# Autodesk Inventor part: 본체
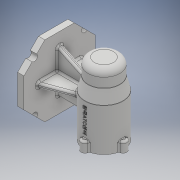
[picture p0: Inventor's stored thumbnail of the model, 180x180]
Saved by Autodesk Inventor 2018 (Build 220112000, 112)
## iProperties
Created: 2019-12
Part Number: 본체
Material: Generic
Document SubType Name: Modeling
Designer: Administrator
Density: 1 g/cm^3
Appearance: Default
Author: Administrator
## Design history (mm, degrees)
sketch "스케치1" dims "d0" = 112
  geometry: L1 (56, -23.196)-(23.196, -56); L2 (23.196, -56)-(-23.196, -56); L3 (-23.196, -56)-(-56, -23.196); L4 (-56, -23.196)-(-56, 23.196); L5 (-56, 23.196)-(-23.196, 56); L6 (-23.196, 56)-(23.196, 56); L7 (23.196, 56)-(56, 23.196); L8 (56, 23.196)-(56, -23.196); 5 further points
  constraints: 16 end point, 3 coincident, 1 horizontal alignment, 1 midpoint, 19 other
extrude "돌출1" new body sketch "스케치1" distance "d1" = 10; taper "d2" = 0 deg
sketch "스케치3"
  geometry: L1 (0, 0)-(-80, 0); L2 (-80, 0)-(-80, -56); L3 (-80, -56)-(-110, -56); L4 (-110, -56)-(-110, -40); L5 (-110, -40)-(-80, -40); L6 (-80, -40)-(-80, -56); L7 (-80, -40)-(-110, -40); L8 (-110, -40)-(-110, 11); L9 (-110, 11)-(-80, 11); L10 (-80, 11)-(-80, -40); L11 (-80, 0)-(-80, 56); L12 (-80, 56)-(-105, 56); L13 (-105, 56)-(-105, 31); L14 (-105, 31)-(-80, 31); L15 (-80, 31)-(-80, 56); L16 (-105, 31)-(-110, 11); L17 (-80, 31)-(-80, 11)
  constraints: 34 end point, 6 parallel, 4 horizontal, 3 perpendicular, 2 vertical, 1 point on line
  dimensions: "d4" = 56 distance of L1.end L2.end; "d5" = 30 distance of L4.end L5.end; "d6" = 16 distance of L3.end L4.end; "d7" = 30 distance of L8.end L9.end; "d8" = 51 distance of L7.end L8.end; "d9" = 56 distance of L1.end L11.end; "d10" = 25 distance of L14.end L13.end; "d11" = 25 distance of L13.end L12.end
revolve "회전1" sketch "스케치3" stored, may be unused: angle "d12" = 90 deg
sketch "스케치4"
  geometry: L1 (0, 0)-(0, 30); L2 (0, 30)-(0, -30); L3 (0, 0)-(-32.316, 0); L4 (-32.316, 0)-(30, 0); L5 (0, 0)-(-30, 0); L6 (-30, 0)-(30, 0); L7 (0, 0)-(-31.297, 0); C1 r 25 at (0, 0) reference; C2 r 6 at (-30, 0); C3 r 6 at (0, -30); C4 r 6 at (0, 30); C5 r 6 at (30, 0); A1 r 30 centre (0, 0) between (30, 0) and (0, 30); A2 r 30 centre (0, 0) between (0, 30) and (0, -30) reference; 1 further point
  constraints: 14 end point, 5 centre point, 5 point on circle, 4 coincident, 1 horizontal, 1 point on line, 1 vertical
  dimensions: "d13" = 12 diameter of C2; "d14" = 12 diameter of C3; "d15" = 12 diameter of C4; "d16" = 12 diameter of C5
extrude "돌출2" join sketch "스케치4" distance "d17" = 16; taper "d18" = 0 deg
sketch "스케치5"
  geometry: L1 (-10, -56)-(-10, -23.196) reference; L2 (-10, -56)-(-10, -31); L3 (-10, -31)-(-69.314, -31); L4 (-10, 23.196)-(-10, 56) reference; L5 (-10, 56)-(-10, 38); L6 (-10, 38)-(-71.6, 9.275); L7 (-71.6, 9.275)-(-69.314, -31); L8 (-10, -31)-(-10, 38); 1 further point
  constraints: 12 end point, 2 point on line, 1 collinear, 1 perpendicular
  dimensions: "d19" = 25 distance of L1.start L2.end; "d20" = 18 distance of L4.end L5.end; "d21" = 115 deg angle of L5 L6
extrude "돌출3" join sketch "스케치5" stored distance "d22" = 8; taper "d23" = 0 deg
node "작업 평면1"
sketch "스케치6"
  geometry: L1 (10, 79.196)-(10, 59.196); L2 (10, 46.392)-(10, 79.196) reference; L3 (10, -32.804)-(10, 0) reference; L4 (10, -32.804)-(10, -12.804); L5 (10, -12.804)-(64.681, 7.098); L6 (10, 59.196)-(75.807, 35.244); L7 (75.807, 35.244)-(64.681, 7.098); L8 (10, 59.196)-(10, -12.804); 1 further point
  constraints: 12 end point, 2 point on line, 1 collinear
  dimensions: "d24" = 20 distance of L1.start L1.end; "d25" = 20 distance of L3.start L4.end; "d26" = 110 deg angle of L4 L5; "d27" = 110 deg angle of L6 L1
extrude "돌출4" join sketch "스케치6" stored distance "d28" = 8; taper "d29" = 0 deg
sketch "스케치7"
  geometry: L1 (0, 0)-(-39.598, 39.598); L2 (0, 0)-(62.448, 0); L3 (0, 0)-(39.598, 39.598); L4 (0, 0)-(80.362, 0); L5 (0, 0)-(39.598, -39.598); L6 (0, 0)-(85.885, 0); L7 (0, 0)-(-39.598, -39.598); L8 (0, 0)-(72.456, 0); L9 (-56, 23.196)-(-23.196, 56) reference; L10 (-56, 23.196)-(-23.196, 56); L11 (-23.196, 56)-(23.196, 56); L12 (23.196, 56)-(56, 23.196); L13 (56, 23.196)-(56, -23.196); L14 (56, -23.196)-(23.196, -56); L15 (23.196, -56)-(-23.196, -56); L16 (-23.196, -56)-(-56, -23.196); L17 (-56, -23.196)-(-56, 23.196); 1 further point
  constraints: 32 end point, 4 horizontal, 4 midpoint, 1 coincident, 17 other
  dimensions: "d30" = 135 deg angle of L2 L1; "d31" = 45 deg angle of L4 L3; "d32" = 45 deg angle of L5 L6; "d33" = 135 deg angle of L7 L8
hole "구멍1" sketch "스케치7" at (39.598, 39.598), (-39.598, -39.598), (39.598, -39.598), (-39.598, 39.598) diameter "d34" = 10; stored, may be unused: countersink angle "d38" = 90 deg, drill point angle "d40" = 118 deg; dims "d35" = 6, "d36" = 4, "d37" = 2, "d39" = 10
sketch "스케치8"
  geometry: L1 (-74, -56)-(-86, -56) reference; L2 (-80, -56)-(-101, -56); L3 (-101, -56)-(-101, -41); L4 (-101, -41)-(-80, -41); L5 (-80, -41)-(-80, -56); L6 (-80, -41)-(-104, -41); L7 (-104, -41)-(-104, 13); L8 (-104, 13)-(-80, 13); L9 (-80, 13)-(-80, -41); L10 (-80, 13)-(-101, 13); L11 (-101, 13)-(-101, 25); L12 (-101, 25)-(-80, 25); L13 (-80, 25)-(-80, 13); L14 (-80, 25)-(-97.5, 25); L15 (-97.5, 25)-(-97.5, 43); L16 (-97.5, 43)-(-80, 43); L17 (-80, 43)-(-80, 25); L18 (-80, 43)-(-96, 43); L19 (-96, 43)-(-96, 47); L20 (-96, 47)-(-80, 47); L21 (-80, 47)-(-80, 43); L22 (-80, 47)-(-90.5, 47); L23 (-90.5, 47)-(-90.5, 50); L24 (-90.5, 50)-(-80, 50); L25 (-80, 50)-(-80, 47); 3 further points
  constraints: 48 end point, 12 parallel, 6 horizontal, 6 perpendicular, 1 midpoint
  dimensions: "d41" = 21 distance of L3.end L4.end; "d42" = 15 distance of L2.end L3.end; "d43" = 24 distance of L7.end L8.end; "d44" = 54 distance of L6.end L7.end; "d45" = 21 distance of L11.end L12.end; "d46" = 12 distance of L10.end L11.end; "d47" = 17.5 distance of L15.end L16.end; "d48" = 18 distance of L14.end L15.end; "d49" = 16 distance of L19.end L20.end; "d50" = 4 distance of L18.end L19.end; "d51" = 10.5 distance of L23.end L24.end; "d52" = 3 distance of L22.end L23.end
revolve "회전2" sketch "스케치8" stored, may be unused: angle "d53" = 90 deg
fillet "모깎기1" dims "d54" = 3
fillet "모깎기2" dims "d55" = 0.3
fillet "모깎기3" dims "d56" = 3
chamfer "모따기1" distance "d57" = 1; stored, may be unused: second distance "d58" = 2, angle "d59" = 45 deg
fillet "모깎기4" dims "d60" = 10
fillet "모깎기5" dims "d61" = 3
fillet "모깎기6" dims "d62" = 3
fillet "모깎기7" dims "d63" = 1
fillet "모깎기8" dims "d64" = 3
fillet "모깎기9" dims "d65" = 3
fillet "모깎기10" dims "d66" = 3
fillet "모깎기11" dims "d67" = 3
sketch "스케치10"
  geometry: L1 (0, -30)-(-30, -30); L2 (-30, -30)-(30, -30); L3 (0, -30)-(0, 0); L4 (0, 0)-(0, -60); C1 r 22 at (0, -30) reference; A1 r 30 centre (0, -30) between (0, -60) and (-30, -30); 1 further point
  constraints: 8 end point, 4 point on circle, 1 centre point, 1 coincident, 1 horizontal, 1 vertical
  dimensions: "d68" = 60 diameter of A1
hole "구멍2" sketch "스케치10" at (0, -60), (-30, -30), (0, 0), (30, -30) diameter "d69" = 3.242; stored, may be unused: countersink angle "d73" = 90 deg, drill point angle "d75" = 118 deg; dims "d70" = 8, "d71" = 4, "d72" = 2, "d74" = 11
node "작업 평면2"
node "작업 평면3"
sketch "스케치13"
  geometry: 1 further point
node "작업 평면4"
node "작업 평면5"
sketch "스케치14"
  geometry: L1 (-22, -8)-(22, -8) reference; 2 further points
  constraints: 1 other
feature "엠보싱1" sketch "스케치14" dims "d0" = 112, "d4" = 56, "d5" = 30, "d6" = 16, "d7" = 30, "d8" = 51, "d9" = 56, "d10" = 25, "d11" = 25, "d78" = 0.5, "d79" = 0
node "솔리드1"
